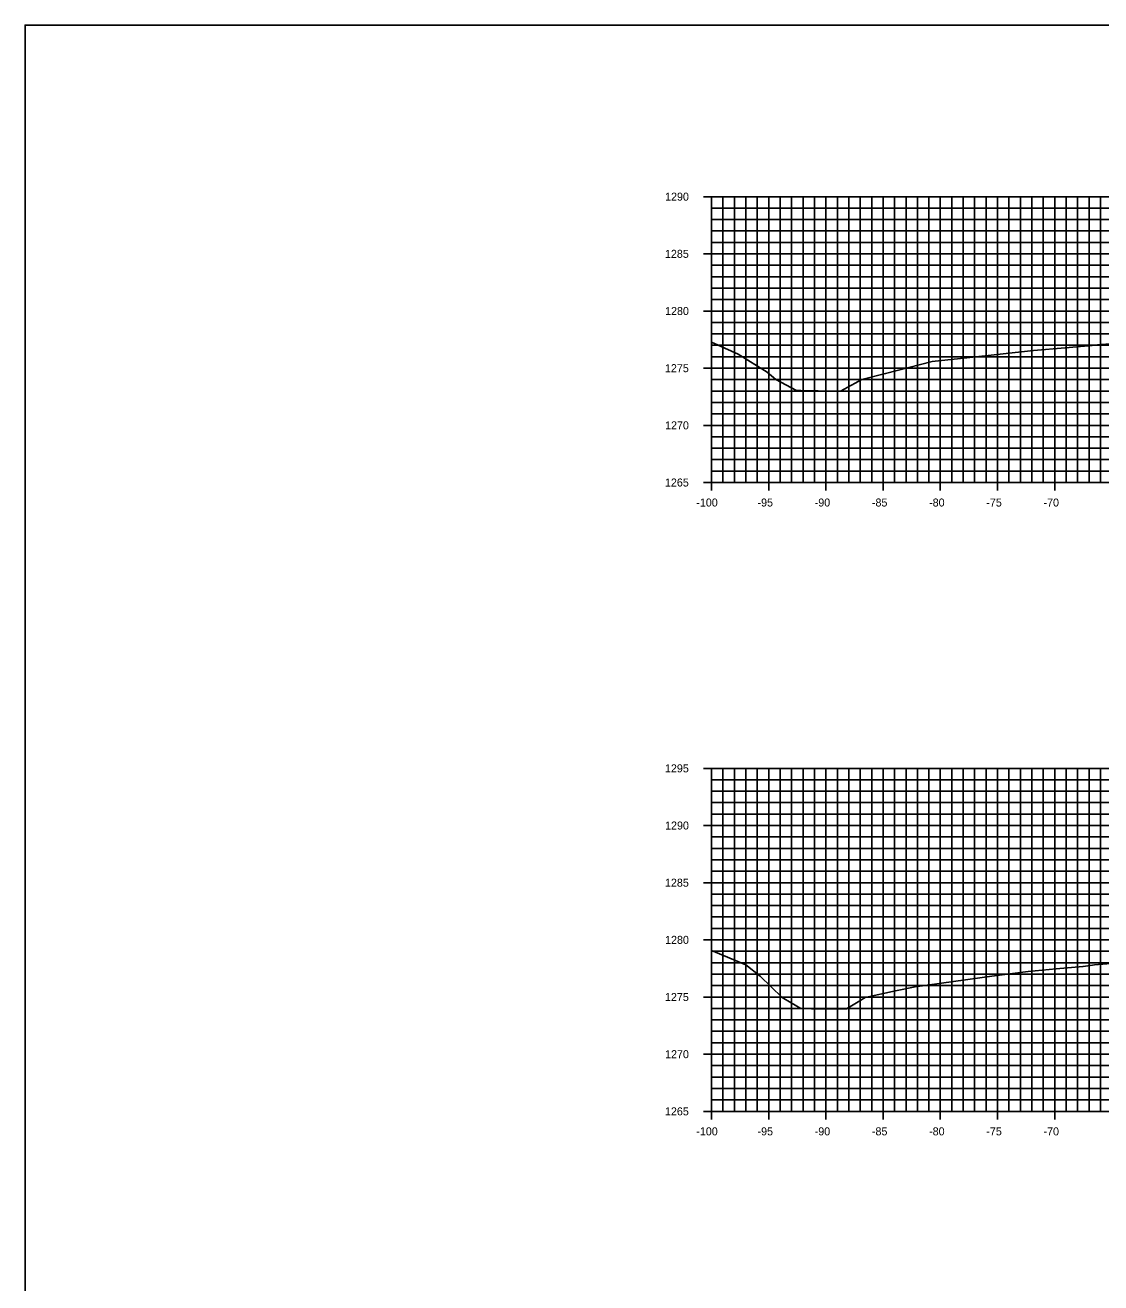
# Model space of a CAD drawing. Extents: x 674939 to 678919, y 750652 to 765176.
# Drawn here: x 678578.5 to 678672.6, y 756092.6 to 756202.6 of the extents above; entities that cross this region are included whole.
import ezdxf

# ---------------------------------------------------------------- set-up
doc = ezdxf.new("R2010")
doc.units = 0
for name, color, linetype in [('Level 10', 7, 'Continuous'), ('Level 20', 7, 'Continuous'), ('Level 4', 7, 'Continuous'), ('Level 8', 7, 'Continuous'), ('Level 9', 7, 'Continuous')]:
    doc.layers.add(name, color=color, linetype=linetype)

msp = doc.modelspace()

# ---------------------------------------------------------------- linework, layer by layer
at = {"layer": 'Level 10'}
for points in [[(678638.53, 756174.81), (678640.87, 756173.78), (678643.4, 756172.2), (678644.14, 756171.56), (678644.64, 756171.3), (678645.91, 756170.64), (678646.78, 756170.58), (678647.14, 756170.56), (678647.86, 756170.56), (678649.79, 756170.55), (678651.09, 756171.25), (678651.66, 756171.55), (678653.75, 756172.07), (678657.83, 756173.12), (678660.84, 756173.45), (678666.66, 756174.09), (678669.45, 756174.34), (678671.8, 756174.54), (678672.27, 756174.58), (678676.24, 756174.9)], [(678638.53, 756121.63), (678641.53, 756120.36), (678642.79, 756119.38), (678644.7, 756117.52), (678645.5, 756117.05), (678646.35, 756116.55), (678647.26, 756116.53), (678648.14, 756116.52), (678649.1, 756116.53), (678650.32, 756116.53), (678651.21, 756117.05), (678651.96, 756117.5), (678654.61, 756118.08), (678656.32, 756118.43), (678663.04, 756119.36), (678666.22, 756119.79), (678668.66, 756120.01), (678670.98, 756120.23), (678671.01, 756120.23), (678671.84, 756120.34), (678672.01, 756120.36), (678676.36, 756120.72)]]:
    msp.add_lwpolyline(points, dxfattribs=at)
at = {"layer": 'Level 20'}
for p, q in [((678638.53, 756187.55), (678838.53, 756187.55)), ((678638.53, 756162.55), (678638.53, 756187.55)), ((678639.53, 756162.55), (678639.53, 756187.55)), ((678640.53, 756162.55), (678640.53, 756187.55)), ((678641.53, 756162.55), (678641.53, 756187.55)), ((678642.53, 756162.55), (678642.53, 756187.55)), ((678643.53, 756162.55), (678643.53, 756187.55)), ((678644.53, 756162.55), (678644.53, 756187.55)), ((678645.53, 756162.55), (678645.53, 756187.55)), ((678646.53, 756162.55), (678646.53, 756187.55)), ((678647.53, 756162.55), (678647.53, 756187.55)), ((678648.53, 756162.55), (678648.53, 756187.55)), ((678649.53, 756162.55), (678649.53, 756187.55)), ((678650.53, 756162.55), (678650.53, 756187.55)), ((678651.53, 756162.55), (678651.53, 756187.55)), ((678652.53, 756162.55), (678652.53, 756187.55)), ((678653.53, 756162.55), (678653.53, 756187.55)), ((678654.53, 756162.55), (678654.53, 756187.55)), ((678655.53, 756162.55), (678655.53, 756187.55)), ((678656.53, 756162.55), (678656.53, 756187.55)), ((678657.53, 756162.55), (678657.53, 756187.55)), ((678658.53, 756162.55), (678658.53, 756187.55)), ((678659.53, 756162.55), (678659.53, 756187.55)), ((678660.53, 756162.55), (678660.53, 756187.55)), ((678661.53, 756162.55), (678661.53, 756187.55)), ((678662.53, 756162.55), (678662.53, 756187.55)), ((678663.53, 756162.55), (678663.53, 756187.55)), ((678664.53, 756162.55), (678664.53, 756187.55)), ((678665.53, 756162.55), (678665.53, 756187.55)), ((678666.53, 756162.55), (678666.53, 756187.55)), ((678667.53, 756162.55), (678667.53, 756187.55)), ((678668.53, 756162.55), (678668.53, 756187.55)), ((678669.53, 756162.55), (678669.53, 756187.55)), ((678670.53, 756162.55), (678670.53, 756187.55)), ((678671.53, 756162.55), (678671.53, 756187.55)), ((678672.53, 756162.55), (678672.53, 756187.55)), ((678638.53, 756186.55), (678838.53, 756186.55)), ((678638.53, 756185.55), (678838.53, 756185.55)), ((678638.53, 756184.55), (678838.53, 756184.55)), ((678638.53, 756183.55), (678838.53, 756183.55)), ((678638.53, 756182.55), (678838.53, 756182.55)), ((678638.53, 756181.55), (678838.53, 756181.55)), ((678638.53, 756180.55), (678838.53, 756180.55)), ((678638.53, 756179.55), (678838.53, 756179.55)), ((678638.53, 756178.55), (678838.53, 756178.55)), ((678638.53, 756177.55), (678838.53, 756177.55)), ((678638.53, 756176.55), (678838.53, 756176.55)), ((678638.53, 756175.55), (678838.53, 756175.55)), ((678638.53, 756174.55), (678838.53, 756174.55)), ((678638.53, 756173.55), (678838.53, 756173.55)), ((678638.53, 756172.55), (678838.53, 756172.55)), ((678638.53, 756171.55), (678838.53, 756171.55)), ((678638.53, 756170.55), (678838.53, 756170.55)), ((678638.53, 756169.55), (678838.53, 756169.55)), ((678638.53, 756168.55), (678838.53, 756168.55)), ((678638.53, 756167.55), (678838.53, 756167.55)), ((678638.53, 756166.55), (678838.53, 756166.55)), ((678638.53, 756165.55), (678838.53, 756165.55)), ((678638.53, 756164.55), (678838.53, 756164.55)), ((678638.53, 756163.55), (678838.53, 756163.55)), ((678638.53, 756162.55), (678838.53, 756162.55)), ((678638.53, 756137.55), (678838.53, 756137.55)), ((678638.53, 756107.55), (678638.53, 756137.55)), ((678639.53, 756107.55), (678639.53, 756137.55)), ((678640.53, 756107.55), (678640.53, 756137.55)), ((678641.53, 756107.55), (678641.53, 756137.55)), ((678642.53, 756107.55), (678642.53, 756137.55)), ((678643.53, 756107.55), (678643.53, 756137.55)), ((678644.53, 756107.55), (678644.53, 756137.55)), ((678645.53, 756107.55), (678645.53, 756137.55)), ((678646.53, 756107.55), (678646.53, 756137.55)), ((678647.53, 756107.55), (678647.53, 756137.55)), ((678648.53, 756107.55), (678648.53, 756137.55)), ((678649.53, 756107.55), (678649.53, 756137.55)), ((678650.53, 756107.55), (678650.53, 756137.55)), ((678651.53, 756107.55), (678651.53, 756137.55)), ((678652.53, 756107.55), (678652.53, 756137.55)), ((678653.53, 756107.55), (678653.53, 756137.55)), ((678654.53, 756107.55), (678654.53, 756137.55)), ((678655.53, 756107.55), (678655.53, 756137.55)), ((678656.53, 756107.55), (678656.53, 756137.55)), ((678657.53, 756107.55), (678657.53, 756137.55)), ((678658.53, 756107.55), (678658.53, 756137.55)), ((678659.53, 756107.55), (678659.53, 756137.55)), ((678660.53, 756107.55), (678660.53, 756137.55)), ((678661.53, 756107.55), (678661.53, 756137.55)), ((678662.53, 756107.55), (678662.53, 756137.55)), ((678663.53, 756107.55), (678663.53, 756137.55)), ((678664.53, 756107.55), (678664.53, 756137.55)), ((678665.53, 756107.55), (678665.53, 756137.55)), ((678666.53, 756107.55), (678666.53, 756137.55)), ((678667.53, 756107.55), (678667.53, 756137.55)), ((678668.53, 756107.55), (678668.53, 756137.55)), ((678669.53, 756107.55), (678669.53, 756137.55)), ((678670.53, 756107.55), (678670.53, 756137.55)), ((678671.53, 756107.55), (678671.53, 756137.55)), ((678672.53, 756107.55), (678672.53, 756137.55)), ((678638.53, 756136.55), (678838.53, 756136.55)), ((678638.53, 756135.55), (678838.53, 756135.55)), ((678638.53, 756134.55), (678838.53, 756134.55)), ((678638.53, 756133.55), (678838.53, 756133.55)), ((678638.53, 756132.55), (678838.53, 756132.55)), ((678638.53, 756131.55), (678838.53, 756131.55)), ((678638.53, 756130.55), (678838.53, 756130.55)), ((678638.53, 756129.55), (678838.53, 756129.55)), ((678638.53, 756128.55), (678838.53, 756128.55)), ((678638.53, 756127.55), (678838.53, 756127.55)), ((678638.53, 756126.55), (678838.53, 756126.55)), ((678638.53, 756125.55), (678838.53, 756125.55)), ((678638.53, 756124.55), (678838.53, 756124.55)), ((678638.53, 756123.55), (678838.53, 756123.55)), ((678638.53, 756122.55), (678838.53, 756122.55)), ((678638.53, 756121.55), (678838.53, 756121.55)), ((678638.53, 756120.55), (678838.53, 756120.55)), ((678638.53, 756119.55), (678838.53, 756119.55)), ((678638.53, 756118.55), (678838.53, 756118.55)), ((678638.53, 756117.55), (678838.53, 756117.55)), ((678638.53, 756116.55), (678838.53, 756116.55)), ((678638.53, 756115.55), (678838.53, 756115.55)), ((678638.53, 756114.55), (678838.53, 756114.55)), ((678638.53, 756113.55), (678838.53, 756113.55)), ((678638.53, 756112.55), (678838.53, 756112.55)), ((678638.53, 756111.55), (678838.53, 756111.55)), ((678638.53, 756110.55), (678838.53, 756110.55)), ((678638.53, 756109.55), (678838.53, 756109.55)), ((678638.53, 756108.55), (678838.53, 756108.55)), ((678638.53, 756107.55), (678838.53, 756107.55))]:
    msp.add_line(p, q, dxfattribs=at)
at = {"layer": 'Level 4'}
msp.add_lwpolyline([(678578.53, 755982.55), (678918.53, 755982.55), (678918.53, 756202.55), (678578.53, 756202.55)], close=True, dxfattribs=at)
at = {"layer": 'Level 8'}
for p, q in [((678637.83, 756187.55), (678639.23, 756187.55)), ((678638.53, 756162.55), (678638.53, 756187.55)), ((678638.53, 756186.55), (678638.88, 756186.55)), ((678638.53, 756185.55), (678638.88, 756185.55)), ((678638.53, 756184.55), (678638.88, 756184.55)), ((678638.53, 756183.55), (678638.88, 756183.55)), ((678637.83, 756182.55), (678639.23, 756182.55)), ((678638.53, 756181.55), (678638.88, 756181.55)), ((678638.53, 756180.55), (678638.88, 756180.55)), ((678638.53, 756179.55), (678638.88, 756179.55)), ((678638.53, 756178.55), (678638.88, 756178.55)), ((678637.83, 756177.55), (678639.23, 756177.55)), ((678638.53, 756176.55), (678638.88, 756176.55)), ((678638.53, 756175.55), (678638.88, 756175.55)), ((678638.53, 756174.55), (678638.88, 756174.55)), ((678638.53, 756173.55), (678638.88, 756173.55)), ((678637.83, 756172.55), (678639.23, 756172.55)), ((678638.53, 756171.55), (678638.88, 756171.55)), ((678638.53, 756170.55), (678638.88, 756170.55)), ((678638.53, 756169.55), (678638.88, 756169.55)), ((678637.83, 756167.55), (678639.23, 756167.55)), ((678638.53, 756168.55), (678638.88, 756168.55)), ((678638.53, 756166.55), (678638.88, 756166.55)), ((678638.53, 756165.55), (678638.88, 756165.55)), ((678638.53, 756164.55), (678638.88, 756164.55)), ((678638.53, 756163.55), (678638.88, 756163.55)), ((678638.53, 756161.85), (678638.53, 756163.25)), ((678643.53, 756161.85), (678643.53, 756163.25)), ((678648.53, 756161.85), (678648.53, 756163.25)), ((678653.53, 756161.85), (678653.53, 756163.25)), ((678658.53, 756161.85), (678658.53, 756163.25)), ((678663.53, 756161.85), (678663.53, 756163.25)), ((678668.53, 756161.85), (678668.53, 756163.25)), ((678637.83, 756162.55), (678639.23, 756162.55)), ((678638.53, 756162.55), (678838.53, 756162.55)), ((678637.83, 756137.55), (678639.23, 756137.55)), ((678638.53, 756107.55), (678638.53, 756137.55)), ((678638.53, 756136.55), (678638.88, 756136.55)), ((678638.53, 756135.55), (678638.88, 756135.55)), ((678638.53, 756134.55), (678638.88, 756134.55)), ((678638.53, 756133.55), (678638.88, 756133.55)), ((678637.83, 756132.55), (678639.23, 756132.55)), ((678638.53, 756131.55), (678638.88, 756131.55)), ((678638.53, 756130.55), (678638.88, 756130.55)), ((678638.53, 756129.55), (678638.88, 756129.55)), ((678638.53, 756128.55), (678638.88, 756128.55)), ((678637.83, 756127.55), (678639.23, 756127.55)), ((678638.53, 756126.55), (678638.88, 756126.55)), ((678638.53, 756125.55), (678638.88, 756125.55)), ((678638.53, 756124.55), (678638.88, 756124.55)), ((678638.53, 756123.55), (678638.88, 756123.55)), ((678637.83, 756122.55), (678639.23, 756122.55)), ((678638.53, 756121.55), (678638.88, 756121.55)), ((678638.53, 756120.55), (678638.88, 756120.55)), ((678638.53, 756119.55), (678638.88, 756119.55)), ((678638.53, 756118.55), (678638.88, 756118.55)), ((678637.83, 756117.55), (678639.23, 756117.55)), ((678638.53, 756116.55), (678638.88, 756116.55)), ((678638.53, 756115.55), (678638.88, 756115.55)), ((678638.53, 756114.55), (678638.88, 756114.55)), ((678637.83, 756112.55), (678639.23, 756112.55)), ((678638.53, 756113.55), (678638.88, 756113.55)), ((678638.53, 756111.55), (678638.88, 756111.55)), ((678638.53, 756110.55), (678638.88, 756110.55)), ((678638.53, 756109.55), (678638.88, 756109.55)), ((678638.53, 756108.55), (678638.88, 756108.55)), ((678638.53, 756106.85), (678638.53, 756108.25)), ((678643.53, 756106.85), (678643.53, 756108.25)), ((678648.53, 756106.85), (678648.53, 756108.25)), ((678653.53, 756106.85), (678653.53, 756108.25)), ((678658.53, 756106.85), (678658.53, 756108.25)), ((678663.53, 756106.85), (678663.53, 756108.25)), ((678668.53, 756106.85), (678668.53, 756108.25)), ((678637.83, 756107.55), (678639.23, 756107.55)), ((678638.53, 756107.55), (678838.53, 756107.55))]:
    msp.add_line(p, q, dxfattribs=at)

# ---------------------------------------------------------------- texts
at = {"layer": 'Level 9'}
for s, p in [('1290', (678634.47, 756187.2)), ('1285', (678634.46, 756182.2)), ('1280', (678634.47, 756177.2)), ('1275', (678634.46, 756172.2)), ('1270', (678634.47, 756167.2)), ('1265', (678634.46, 756162.2)), ('-100', (678637.2, 756160.45)), ('-95', (678642.55, 756160.45)), ('-90', (678647.55, 756160.45)), ('-85', (678652.55, 756160.45)), ('-80', (678657.55, 756160.45)), ('-75', (678662.55, 756160.45)), ('-70', (678667.55, 756160.45)), ('1295', (678634.46, 756137.2)), ('1290', (678634.47, 756132.2)), ('1285', (678634.46, 756127.2)), ('1280', (678634.47, 756122.2)), ('1275', (678634.46, 756117.2)), ('1270', (678634.47, 756112.2)), ('1265', (678634.46, 756107.2)), ('-100', (678637.2, 756105.45)), ('-95', (678642.55, 756105.45)), ('-90', (678647.55, 756105.45)), ('-85', (678652.55, 756105.45)), ('-80', (678657.55, 756105.45)), ('-75', (678662.55, 756105.45)), ('-70', (678667.55, 756105.45))]:
    msp.add_text(s, height=0.7, dxfattribs=at).set_placement(p)

doc.saveas('drawing.dxf')
